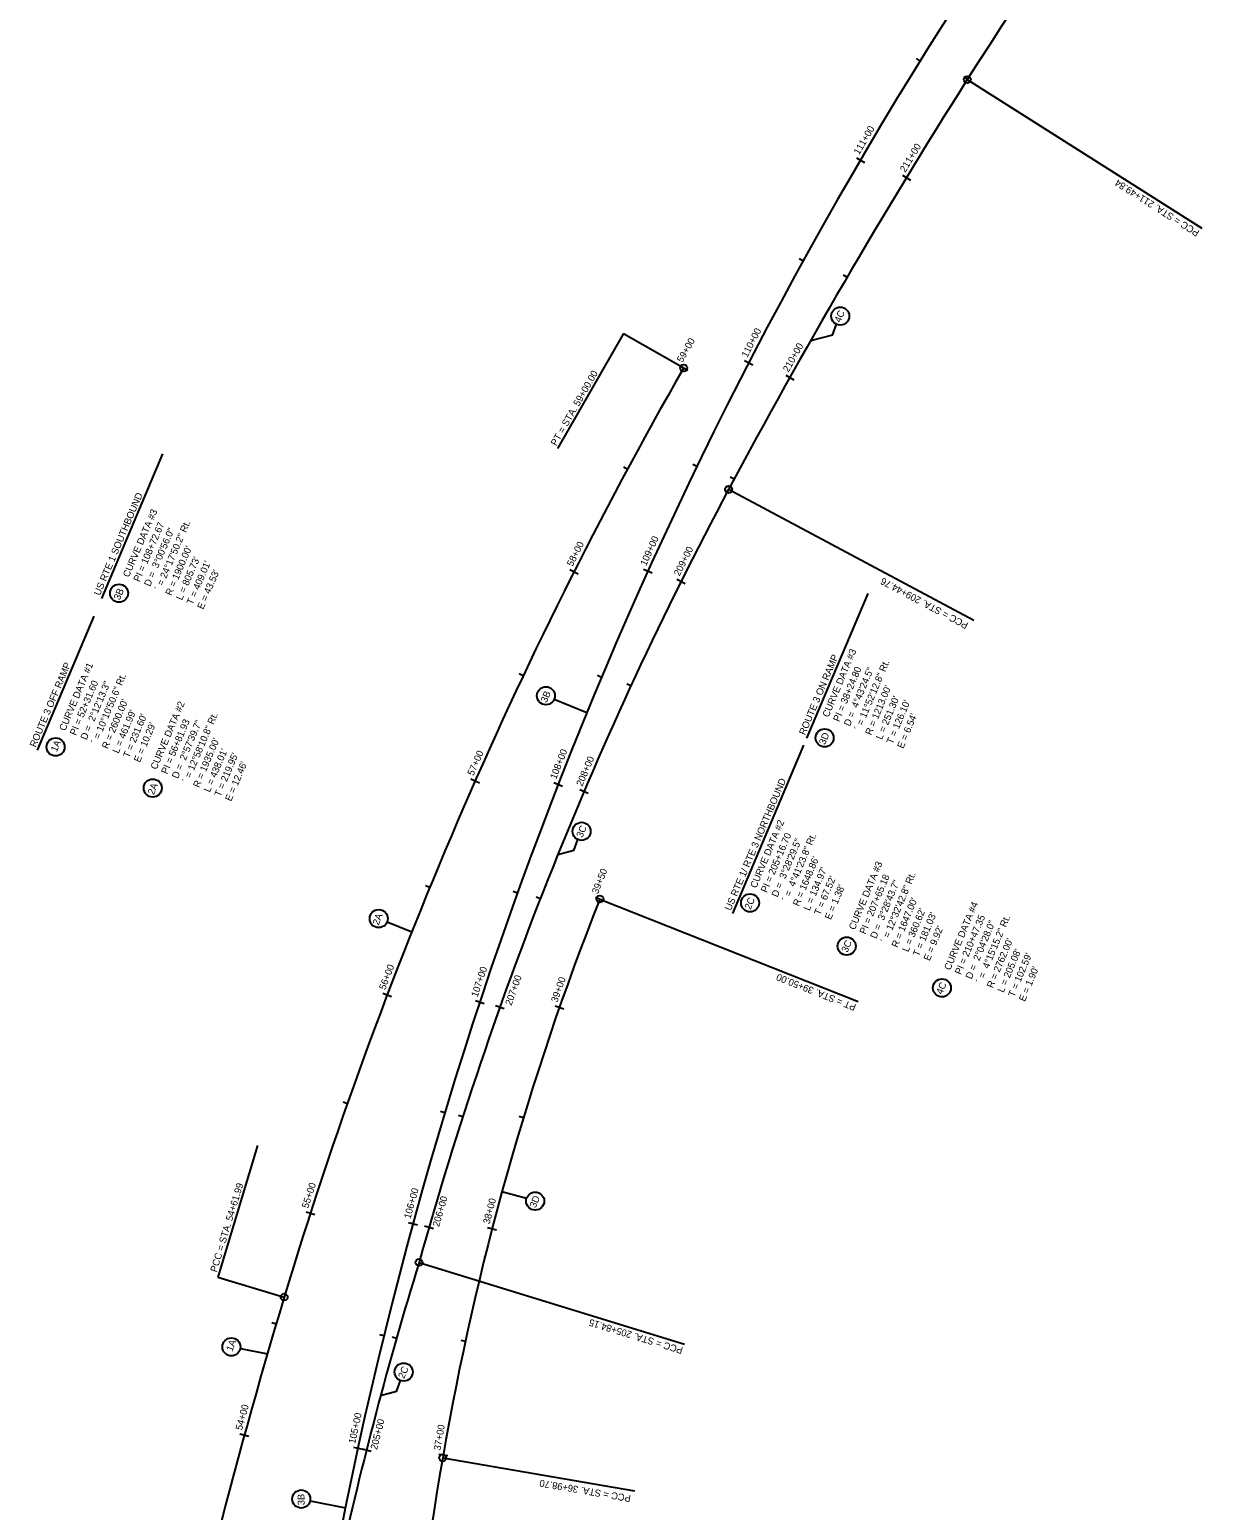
# Model space of a CAD drawing. Extents: x 1667099 to 1669772, y 337408 to 340124.
# Drawn here: x 1667256 to 1667767, y 338082 to 338722 of the extents above; entities that cross this region are included whole.
import ezdxf

# ---------------------------------------------------------------- set-up
doc = ezdxf.new("R2010")
doc.units = 0
for name, color, linetype in [('Alignment', 7, 'Continuous'), ('ANNOTATION', 7, 'Continuous'), ('D_Roadway_Centerline', 7, 'Continuous'), ('D_Roadway_Centerline_CurveData', 7, 'Continuous'), ('D_Roadway_Centerline_Flags', 7, 'Continuous'), ('D_Roadway_Centerline_Text', 7, 'Continuous'), ('S_Roadway_Edge_Pavement', 7, 'Continuous')]:
    doc.layers.add(name, color=color, linetype=linetype)

msp = doc.modelspace()

# ---------------------------------------------------------------- linework, layer by layer
at = {"layer": 'Alignment'}
for centre, radius, start, end in [((1669660.52, 337433.83), 2367, 133.53618, 147.66044), ((1669994.25, 337222.53), 2762, 147.66044, 151.91466), ((1669218.21, 337615.48), 1935, 150.25689, 163.22657), ((1669010.58, 337747.52), 1647, 151.91115, 164.45638), ((1668629.47, 337898.69), 1213, 158.36409, 170.23431), ((1668999.64, 337703.58), 1648.86, 162.88335, 167.57328), ((1669854.92, 337423.57), 2600, 163.22657, 173.40729), ((1669503.61, 337748.23), 2100, 170.2343, 184.08246)]:
    msp.add_arc(centre, radius, start, end, dxfattribs=at)
at = {"layer": 'ANNOTATION'}
for p, q in [((1667602.4, 338589.61), (1667604.1, 338594.32)), ((1667602.4, 338589.61), (1667592.91, 338587.15)), ((1667286.72, 338475.79), (1667313.15, 338538.26)), ((1667591.39, 338415.51), (1667617.82, 338477.98)), ((1667259, 338410.24), (1667283.48, 338468.12)), ((1667482.23, 338432.27), (1667496.3, 338426.49)), ((1667559.3, 338339.63), (1667590.11, 338412.48)), ((1667490.65, 338366.95), (1667483.73, 338365.03)), ((1667490.65, 338366.95), (1667492.35, 338371.66)), ((1667410.01, 338336.04), (1667420.68, 338331.79)), ((1667470.21, 338216.44), (1667459.62, 338219.34)), ((1667346.6, 338151.72), (1667358.28, 338149.37)), ((1667414.13, 338133.14), (1667415.83, 338137.85)), ((1667414.13, 338133.14), (1667407.21, 338131.23)), ((1667376.75, 338085.91), (1667391.97, 338082.83))]:
    msp.add_line(p, q, dxfattribs=at)
for centre in [(1667605.75, 338597.85), (1667294.19, 338478.09), (1667478.62, 338433.75), (1667599.03, 338415.54), (1667266.78, 338411.64), (1667308.76, 338393.89), (1667494.02, 338375.18), (1667566.81, 338344.23), (1667406.37, 338337.45), (1667608.56, 338325.56), (1667649.68, 338307.51), (1667473.97, 338215.4), (1667342.76, 338152.37), (1667417.16, 338141.52), (1667372.92, 338086.65)]:
    msp.add_circle(centre, 3.9, dxfattribs=at)
at = {"layer": 'D_Roadway_Centerline'}
for centre, radius, start, end in [((1669660.52, 337433.83), 2367, 133.53618, 147.66044), ((1669254.06, 337705.17), 1900, 144.54079, 168.83807), ((1669994.25, 337222.53), 2762, 147.66044, 151.91466), ((1669218.21, 337615.48), 1935, 150.25689, 163.22657), ((1669010.58, 337747.52), 1647, 151.91115, 164.45638), ((1668629.47, 337898.69), 1213, 158.36409, 170.23431), ((1668999.64, 337703.58), 1648.86, 162.88335, 167.57328), ((1669854.92, 337423.57), 2600, 163.22657, 173.40729), ((1669503.61, 337748.23), 2100, 170.2343, 184.08246)]:
    msp.add_arc(centre, radius, start, end, dxfattribs=at)
at = {"layer": 'D_Roadway_Centerline_Flags'}
for p, q in [((1667512.09, 338590.34), (1667483.64, 338540.55)), ((1667353.94, 338239.35), (1667336.82, 338182.55))]:
    msp.add_line(p, q, dxfattribs=at)
for points in [[(1667660.66, 338700.02), (1667762.05, 338635.83)], [(1667512.09, 338590.34), (1667538.13, 338575.45)], [(1667557.57, 338522.99), (1667663.43, 338466.49)], [(1667501.93, 338345.93), (1667613.47, 338301.68)], [(1667423.82, 338188.87), (1667538.5, 338153.55)], [(1667336.82, 338182.55), (1667365.54, 338173.89)], [(1667434.04, 338104.43), (1667516.93, 338090.17)]]:
    msp.add_lwpolyline(points, dxfattribs=at)
for centre in [(1667660.66, 338700.02), (1667538.13, 338575.45), (1667557.49, 338522.84), (1667557.57, 338522.99), (1667501.93, 338345.93), (1667423.82, 338188.87), (1667365.54, 338173.89), (1667434.04, 338104.43)]:
    msp.add_circle(centre, 1.5, dxfattribs=at)
at = {"layer": 'D_Roadway_Centerline_Text'}
for points in [[(1667638.59, 338709.11), (1667640.29, 338708.05)], [(1667659.05, 338701.22), (1667660.74, 338700.15)], [(1667612.74, 338666.25), (1667616.19, 338664.23)], [(1667632.67, 338658.71), (1667636.09, 338656.63)], [(1667588.02, 338622.73), (1667589.77, 338621.77)], [(1667607.06, 338615.73), (1667608.79, 338614.72)], [(1667564.45, 338578.58), (1667568, 338576.74)], [(1667536.4, 338576.45), (1667539.87, 338574.46)], [(1667582.23, 338572.29), (1667585.72, 338570.33)], [(1667512.13, 338532.67), (1667513.89, 338531.72)], [(1667542.05, 338533.82), (1667543.85, 338532.94)], [(1667558.19, 338528.4), (1667559.96, 338527.46)], [(1667489, 338488.29), (1667492.57, 338486.48)], [(1667520.84, 338488.48), (1667524.49, 338486.83)], [(1667535.24, 338484.11), (1667538.82, 338482.32)], [(1667467.03, 338443.32), (1667468.84, 338442.46)], [(1667500.83, 338442.6), (1667502.67, 338441.83)], [(1667513.56, 338438.99), (1667515.38, 338438.15)], [(1667446.22, 338397.8), (1667449.88, 338396.18)], [(1667482.03, 338396.22), (1667485.76, 338394.76)], [(1667493.26, 338393.23), (1667496.94, 338391.66)], [(1667426.6, 338351.75), (1667428.45, 338350.99)], [(1667464.46, 338349.35), (1667466.35, 338348.67)], [(1667474.36, 338346.88), (1667476.22, 338346.15)], [(1667500.07, 338346.67), (1667503.79, 338345.19)], [(1667500.07, 338346.67), (1667503.79, 338345.19)], [(1667408.18, 338305.22), (1667411.92, 338303.79)], [(1667448.13, 338302.04), (1667451.93, 338300.78)], [(1667456.88, 338299.97), (1667460.65, 338298.63)], [(1667482.57, 338299.74), (1667486.34, 338298.42)], [(1667390.96, 338258.22), (1667392.85, 338257.56)], [(1667433.05, 338254.31), (1667434.97, 338253.74)], [(1667440.82, 338252.56), (1667442.73, 338251.94)], [(1667467.01, 338252.14), (1667468.93, 338251.56)], [(1667374.97, 338210.79), (1667378.77, 338209.57)], [(1667419.23, 338206.21), (1667423.09, 338205.15)], [(1667426.22, 338204.67), (1667430.06, 338203.57)], [(1667453.44, 338203.94), (1667457.31, 338202.93)], [(1667360.19, 338162.98), (1667362.11, 338162.41)], [(1667406.69, 338157.75), (1667408.63, 338157.28)], [(1667412.18, 338156.68), (1667414.11, 338156.13)], [(1667441.86, 338155.22), (1667443.81, 338154.79)], [(1667346.43, 338114.87), (1667350.29, 338113.81)], [(1667395.42, 338108.99), (1667399.33, 338108.14)], [(1667399.17, 338108.34), (1667403.05, 338107.36)], [(1667432.29, 338106.06), (1667436.24, 338105.38)]]:
    msp.add_lwpolyline(points, dxfattribs=at)
at = {"layer": 'S_Roadway_Edge_Pavement'}
msp.add_arc((1669254.06, 337705.17), 1900, 144.54079, 168.83807, dxfattribs=at)

# ---------------------------------------------------------------- texts
at = {"layer": 'ANNOTATION'}
for s, rotation, p in [('4C', 67.07441, (1667605.86, 338594.81)), ('US RTE 1 SOUTHBOUND', 67.07441, (1667285.92, 338476.82)), ('3B', 67.07441, (1667294.48, 338474.88)), ('ROUTE 3 ON RAMP', 67.07441, (1667590.59, 338416.54)), ('ROUTE 3 OFF RAMP', 67.07441, (1667258.19, 338411.27)), ('3B', 67.07441, (1667478.91, 338430.54)), ('3D', 67.07441, (1667599.19, 338412.36)), ('1A', 67.07441, (1667267.29, 338409.27)), ('US RTE 1/ RTE 3 NORTHBOUND', 67.07441, (1667558.49, 338340.66)), ('2A', 67.07441, (1667309.17, 338390.74)), ('3C', 67.07441, (1667494.35, 338372.22)), ('2C', 67.07441, (1667567, 338341.13)), ('2A', 68.84853, (1667406.34, 338334.43)), ('3C', 67.07441, (1667608.88, 338322.6)), ('4C', 67.07441, (1667649.79, 338304.47)), ('3D', 67.07441, (1667474.13, 338212.22)), ('1A', 68.84853, (1667343.09, 338150.2)), ('2C', 67.07441, (1667417.35, 338138.42)), ('3B', 90.79092, (1667374.36, 338083.99))]:
    msp.add_text(s, height=3, rotation=rotation, dxfattribs=at).set_placement(p)
at = {"layer": 'D_Roadway_Centerline_CurveData'}
for s, rotation, p in [('CURVE DATA #3', 66.68943, (1667298.42, 338484.72)), ('PI = 108+72.67', 66.68943, (1667303.01, 338482.74)), ('´ = 24%%d17\'50.2" Rt.', 66.68943, (1667312.19, 338478.78)), ('D =  3%%d00\'56.0"', 66.68943, (1667307.6, 338480.76)), ("R = 1900.00'", 66.68943, (1667316.78, 338476.81)), ("L = 805.73'", 66.68943, (1667321.38, 338474.83)), ("T = 409.01'", 66.68943, (1667325.97, 338472.85)), ("E = 43.53'", 66.68943, (1667330.56, 338470.87)), ('CURVE DATA #3', 67.30945, (1667600.7, 338424.22)), ('CURVE DATA #1', 67.19616, (1667270.92, 338418.32)), ('PI = 38+24.80', 67.30945, (1667605.32, 338422.29)), ('D =  4%%d43\'24.5"', 67.30945, (1667609.93, 338420.36)), ('´ = 11%%d52\'12.8" Rt.', 67.30945, (1667614.54, 338418.43)), ('PI = 52+31.60', 67.19616, (1667275.53, 338416.38)), ('D =  2%%d12\'13.3"', 67.19616, (1667280.14, 338414.45)), ('´ = 10%%d10\'50.6" Rt.', 67.19616, (1667284.75, 338412.51)), ("R = 1213.00'", 67.30945, (1667619.16, 338416.5)), ("R = 2600.00'", 67.19616, (1667289.36, 338410.57)), ('CURVE DATA #2', 66.98957, (1667310.39, 338401.62)), ("L = 251.30'", 67.30945, (1667623.77, 338414.57)), ("T = 126.10'", 67.30945, (1667628.38, 338412.65)), ("L = 461.99'", 67.19616, (1667293.97, 338408.63)), ("T = 231.60'", 67.19616, (1667298.58, 338406.69)), ('PI = 56+81.93', 66.98957, (1667314.99, 338399.66)), ('´ = 12%%d58\'10.8" Rt.', 66.98957, (1667324.2, 338395.75)), ("E = 6.54'", 67.30945, (1667633, 338410.72)), ("E = 10.29'", 67.19616, (1667303.19, 338404.76)), ('D =  2%%d57\'39.7"', 66.98957, (1667319.6, 338397.71)), ("R = 1935.00'", 66.98957, (1667328.8, 338393.8)), ("L = 438.01'", 66.98957, (1667333.4, 338391.84)), ("T = 219.95'", 66.98957, (1667338, 338389.89)), ("E = 12.46'", 66.98957, (1667342.61, 338387.93)), ('CURVE DATA #2', 67.09773, (1667569.47, 338350.37)), ('PI = 205+16.70', 67.09773, (1667574.07, 338348.42)), ('´ =  4%%d41\'23.8" Rt.', 67.09773, (1667583.29, 338344.53)), ('D =  3%%d28\'29.5"', 67.09773, (1667578.68, 338346.47)), ("R = 1648.86'", 67.09773, (1667587.89, 338342.58)), ("L = 134.97'", 67.09773, (1667592.5, 338340.64)), ('CURVE DATA #3', 67.49106, (1667612.07, 338332.37)), ("T = 67.52'", 67.09773, (1667597.1, 338338.69)), ('PI = 207+65.18', 67.49106, (1667616.69, 338330.46)), ('D =  3%%d28\'43.7"', 67.49106, (1667621.31, 338328.54)), ('´ = 12%%d32\'42.8" Rt.', 67.49106, (1667625.93, 338326.63)), ("E = 1.38'", 67.09773, (1667601.71, 338336.74)), ("R = 1647.00'", 67.49106, (1667630.54, 338324.71)), ("L = 360.62'", 67.49106, (1667635.16, 338322.8)), ("T = 181.03'", 67.49106, (1667639.78, 338320.89)), ('CURVE DATA #4', 67.26677, (1667653.28, 338314.93)), ("E = 9.92'", 67.49106, (1667644.4, 338318.97)), ('PI = 210+47.35', 67.26677, (1667657.89, 338313)), ('D =  2%%d04\'28.0"', 67.26677, (1667662.5, 338311.06)), ('´ =  4%%d15\'15.2" Rt.', 67.26677, (1667667.11, 338309.13)), ("R = 2762.00'", 67.26677, (1667671.72, 338307.2)), ("L = 205.08'", 67.26677, (1667676.33, 338305.27)), ("T = 102.59'", 67.26677, (1667680.95, 338303.34)), ("E = 1.90'", 67.26677, (1667685.56, 338301.4))]:
    msp.add_text(s, height=3, rotation=rotation, dxfattribs=at).set_placement(p)
at = {"layer": 'D_Roadway_Centerline_Flags'}
for s, rotation, p in [('PCC = STA. 211+49.84', 147.66044, (1667761.24, 338634.56)), ('PT = STA. 59+00.00', 60.25689, (1667483.07, 338541.48)), ('PCC = STA. 209+44.76', 151.91115, (1667661.39, 338465.11)), ('PT = STA. 39+50.00', 158.36409, (1667612.92, 338300.29)), ('PCC = STA. 54+61.99', 73.16287, (1667336.39, 338184.46)), ('PCC = STA. 205+84.15', 162.88335, (1667538.06, 338152.11)), ('PCC = STA. 36+98.70', 170.2343, (1667515.47, 338088.25))]:
    msp.add_text(s, height=3, rotation=rotation, dxfattribs=at).set_placement(p)
at = {"layer": 'D_Roadway_Centerline_Text'}
for s, rotation, p in [('111+00', 59.64875, (1667613.93, 338667.29)), ('211+00', 58.69441, (1667633.88, 338659.73)), ('110+00', 62.66431, (1667565.58, 338579.68)), ('59+00', 60.25689, (1667537.58, 338577.5)), ('210+00', 60.76884, (1667583.4, 338573.35)), ('58+00', 63.21791, (1667490.12, 338489.4)), ('109+00', 65.67988, (1667521.91, 338489.64)), ('209+00', 63.46843, (1667536.36, 338485.23)), ('57+00', 66.17894, (1667447.29, 338398.97)), ('108+00', 68.69545, (1667483.04, 338397.43)), ('208+00', 66.94723, (1667494.31, 338394.41)), ('39+50', 68.36409, (1667501.09, 338347.88)), ('39+50', 68.36409, (1667501.09, 338347.88)), ('56+00', 69.13996, (1667409.18, 338306.44)), ('107+00', 71.71101, (1667449.08, 338303.31)), ('207+00', 70.42602, (1667463.71, 338299.69)), ('39+00', 70.72582, (1667483.53, 338301)), ('55+00', 72.10098, (1667375.9, 338212.07)), ('106+00', 74.72658, (1667420.11, 338207.52)), ('206+00', 73.90482, (1667432.42, 338204.05)), ('38+00', 75.4493, (1667454.3, 338205.27)), ('54+00', 74.59255, (1667347.32, 338116.18)), ('105+00', 77.74215, (1667396.22, 338110.35)), ('205+00', 75.80728, (1667405.64, 338107.73)), ('37+00', 80.17278, (1667433.04, 338107.45))]:
    msp.add_text(s, height=3, rotation=rotation, dxfattribs=at).set_placement(p)

doc.saveas('drawing.dxf')
